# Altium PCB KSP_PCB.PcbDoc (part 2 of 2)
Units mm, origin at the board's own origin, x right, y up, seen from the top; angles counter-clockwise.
Board outline 121 x 121 mm, 2 copper layers (Top Layer, Bottom Layer), stack 1.571 mm thick; 210 components, 141 nets, 724 pads, 132 vias.
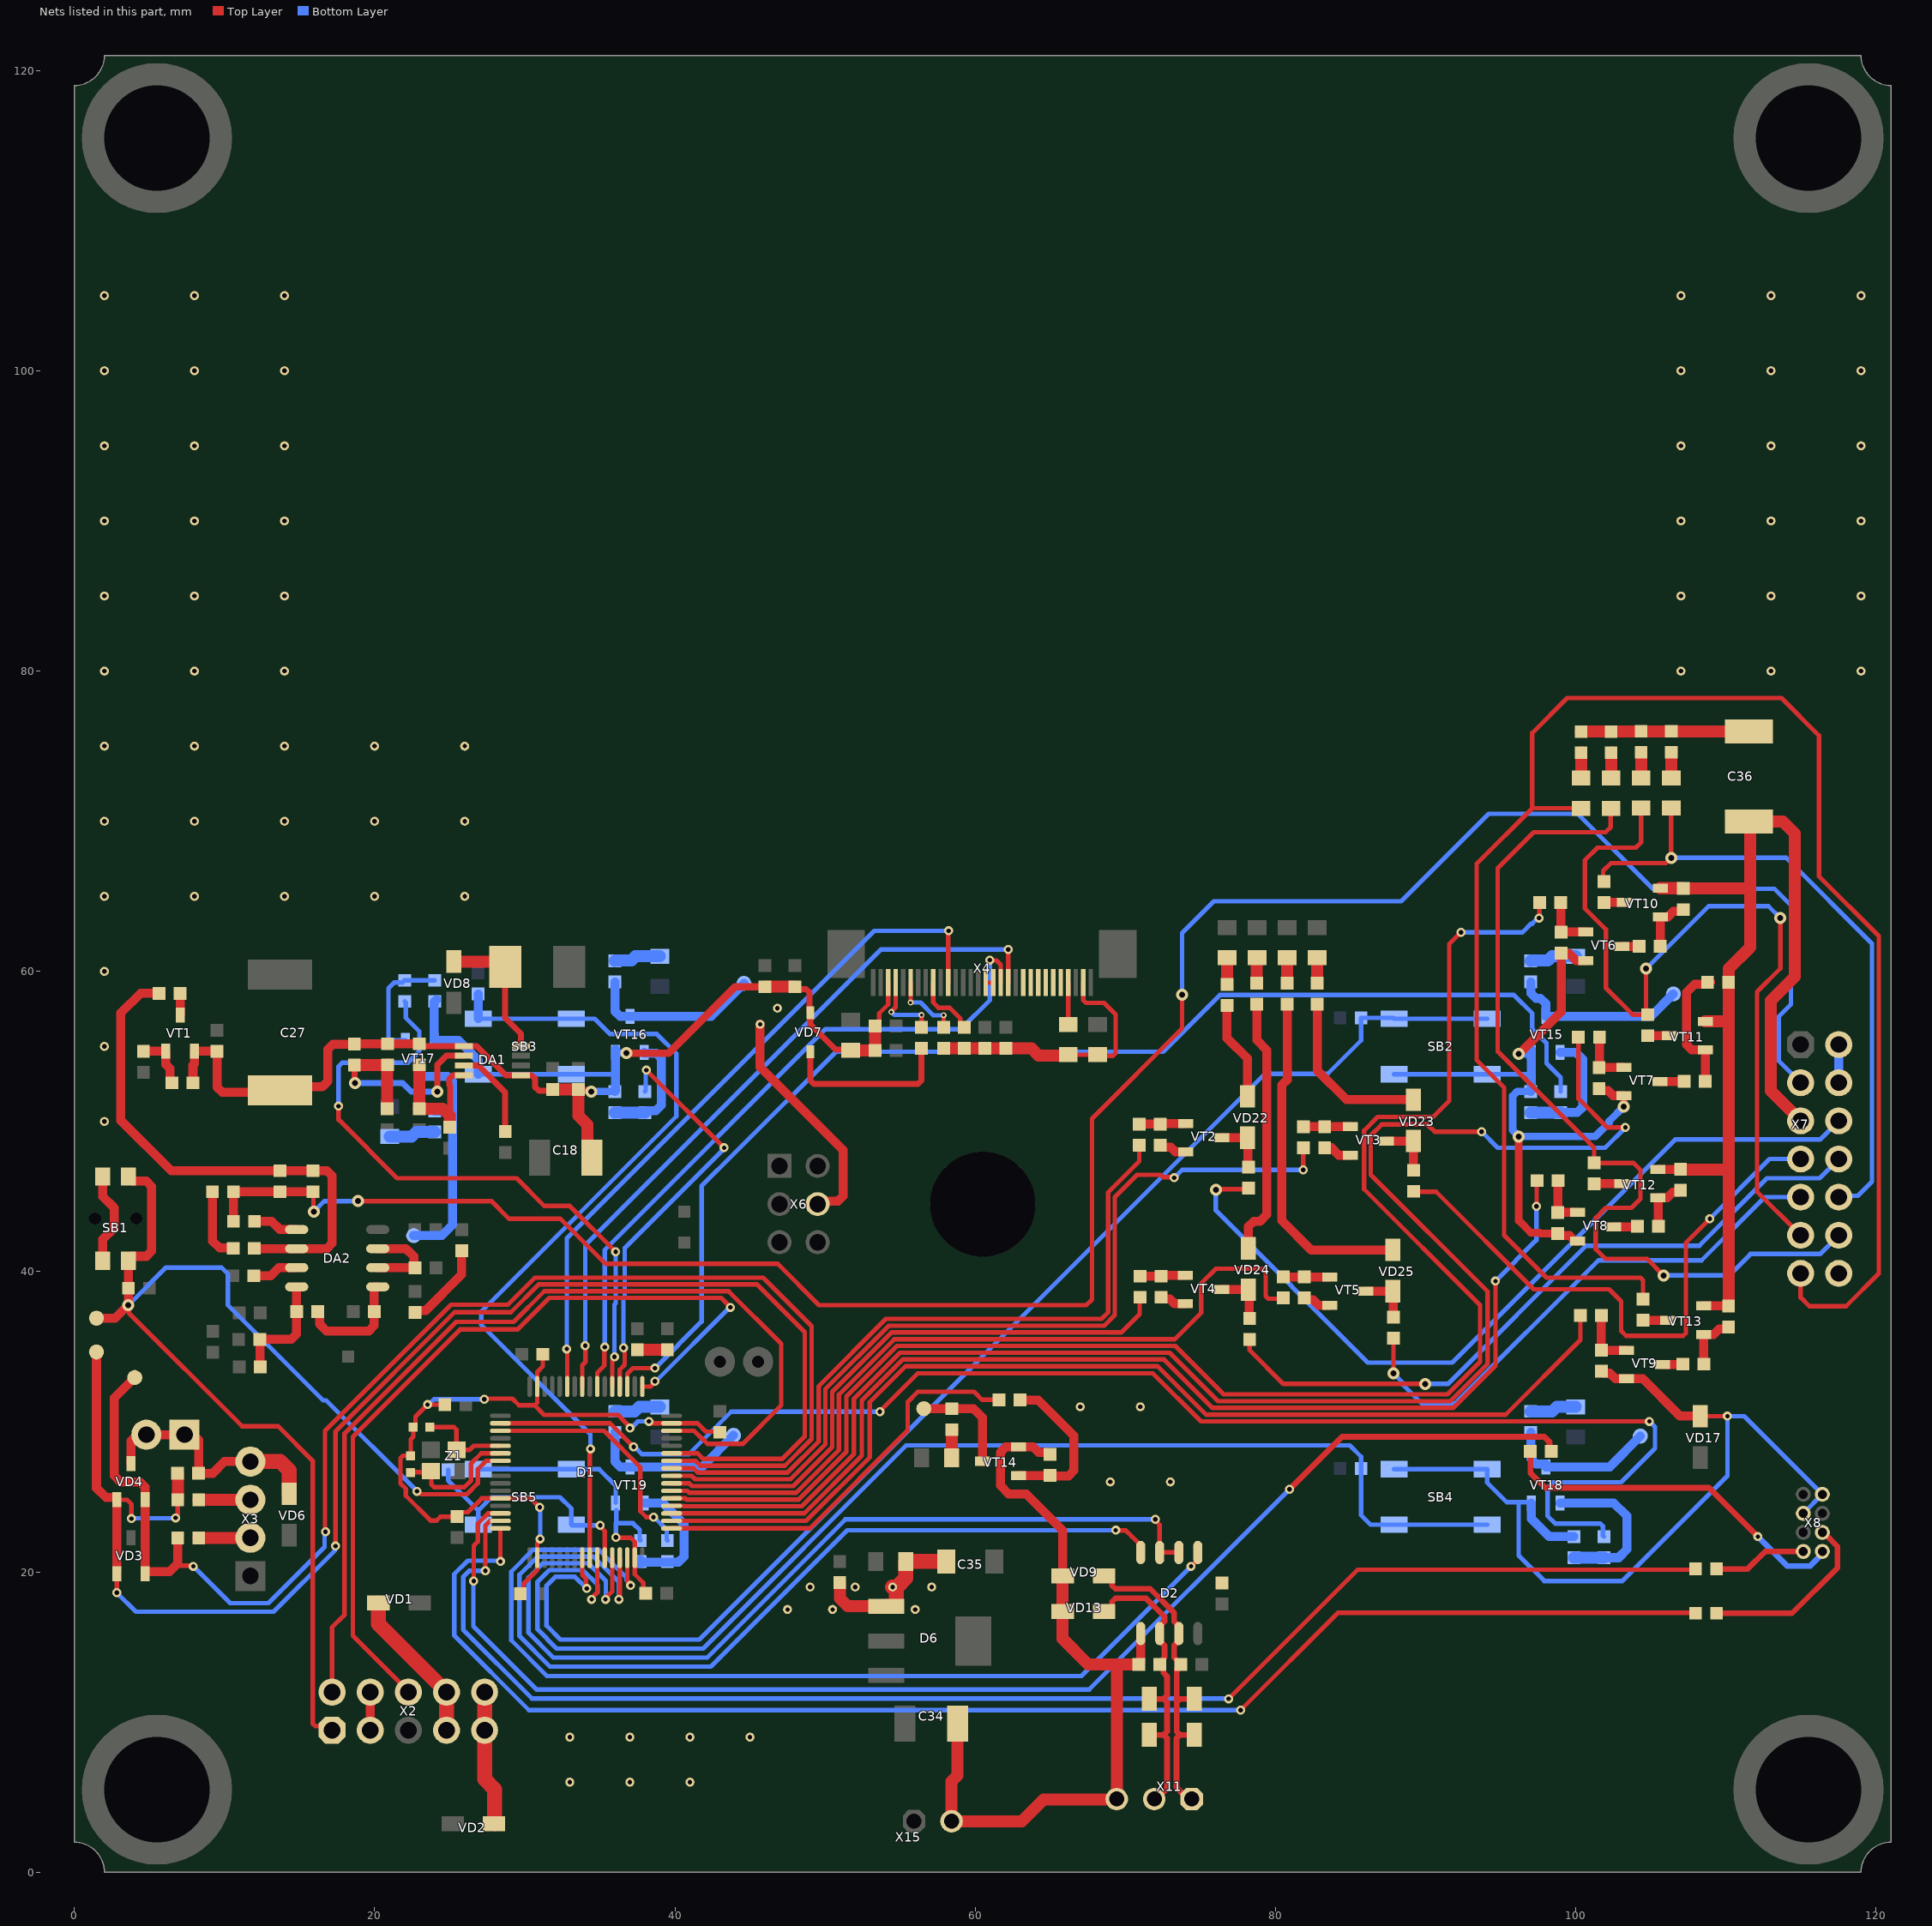
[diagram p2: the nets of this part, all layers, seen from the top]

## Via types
v1: diameter 0.6, hole 0.3, Top Layer to Bottom Layer, tented both sides, 85 vias
v2: diameter 0.8, hole 0.4, Top Layer to Bottom Layer, tented both sides, 42 vias
v3: diameter 0.4, hole 0.2, Top Layer to Bottom Layer, tented both sides, 4 vias
v4: diameter 0.6, hole 0.3, Top Layer to Bottom Layer, 1 vias

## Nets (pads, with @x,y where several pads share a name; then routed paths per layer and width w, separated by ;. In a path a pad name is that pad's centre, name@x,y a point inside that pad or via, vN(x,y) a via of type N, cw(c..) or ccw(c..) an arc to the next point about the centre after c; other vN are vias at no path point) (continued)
GND: C1.1 C2.1 C3.1 C4.1 C5.1 C6.1 C7.1 C8.1 C9.1 C10.1 C11.1 C12.1 C13.1 C14.1 C15.1 C16.1 C17.1 C18.2 C19.1 C20.1 C21.1 C22.1 C24.1 C25.1 C27.2 C28.1 C32.1 C33.1 C34.2 C35.2 C36.2 D1.12 D1.18 D1.31 D1.47 D1.63 D2.5 D6.1 DA1.1 DA1.5 DA2.4 pad.N@2,50 pad.N@2,55 pad.N@2,60 pad.N@2,65 pad.N@2,70 pad.N@2,75 pad.N@2,80 pad.N@2,85 pad.N@2,90 pad.N@2,95 pad.N@2,100 pad.N@2,105 pad.N@8,65 pad.N@8,70 pad.N@8,75 pad.N@8,80 pad.N@8,85 pad.N@8,90 pad.N@8,95 pad.N@8,100 pad.N@8,105 pad.N@14,65 pad.N@14,70 pad.N@14,75 pad.N@14,80 pad.N@14,85 pad.N@14,90 pad.N@14,95 pad.N@14,100 pad.N@14,105 pad.N@20,65 pad.N@20,70 pad.N@20,75 pad.N@26,65 pad.N@26,70 pad.N@26,75 pad.N@33,6 pad.N@33,9 pad.N@37,6 pad.N@37,9 pad.N@41,6 pad.N@41,9 pad.N@45,9 pad.N@45.675,56.475 pad.N@46.825,57.55 pad.N@47.5,17.5 pad.N@49,19 pad.N@50.5,17.5 pad.N@52,19 pad.N@54.5,19 pad.N@56,17.5 pad.N@57.1,19 pad.N@67,31 pad.N@69,26 pad.N@71,31 pad.N@73,26 pad.N@107,80 pad.N@107,85 pad.N@107,90 pad.N@107,95 pad.N@107,100 pad.N@107,105 pad.N@113,80 pad.N@113,85 pad.N@113,90 pad.N@113,95 pad.N@113,100 pad.N@113,105 pad.N@119,80 pad.N@119,85 pad.N@119,90 pad.N@119,95 pad.N@119,100 pad.N@119,105 R1.1 R4.2 R7.1 R8.1 R10.1 R12.2 R16.2 R17.1 R22.2 R23.2 R24.2 R26.2 R31.2 R43.2 R62.1 R63.1 R64.1 R65.1 R74.1 R75.1 R76.1 R77.1 R95.1 R100.1 R101.1 R111.1 R112.1 R113.1 SB1.2 SB2.2 SB3.2 SB4.2 SB5.2 VD4.3 VD6.1 VD7.2 VD9.1 VD13.1 VD17.1 VD26.2 VD27.2 VD28.2 VD29.2 VT1.3 VT2.3 VT3.3 VT4.3 VT5.3 VT6.3 VT7.3 VT8.3 VT9.3 VT14.3 VT15.3 VT16.3 VT17.3 VT18.3 VT19.3 X2.3 X2.4 X3.4 X4.2 X4.5 X4.6 X4.7 X4.8 X4.9 X4.10 X4.14 X4.15 X4.28 X5.1 X5.2 X6.4 X7.2 X7.4 X7.14 X8.2 X8.3 X11.3 X15.2 | length 429.8
  Top Layer w0.3: C1.1@22.4,27.725 22.375,27.75 21.901,27.75 21.725,27.574 21.725,25.9 22.075,25.55 22.075,25.075 23.725,23.425 24.137,23.425 24.387,23.675 25.625,23.675 25.625,23.825 25.775,23.975 26.214,23.975 27.139,24.9 D1.12@28.375,24.9 30.398,24.9 30.998,24.3 v1(31,24.3) ; C1.1@22.4,27.84 22.4,28.825 22.575,29 C4.1@22.575,29.65 22.725,29.8 22.725,30.35 v1(23.525,31.15) C8.1@24.675,31.15 ; v1(27.3,31.5) 27.35,31.55 29.165,31.55 29.615,31.1 30.649,31.1 ; C7.1@29.699,18.549 29.917,18.767 29.917,19.217 30.825,20.125 D1.18@30.825,20.95 30.825,21.919 31.025,22.119 v1(31.025,22.2) ; C3.1@31.2,34.5 31.2,33.7 30.825,33.325 D1.63@30.825,32.35 30.825,31.276 30.649,31.1 ; v4@36.1,22.25 36.132,22.282 37.042,22.282 37.325,21.999 D1.31@37.325,20.95 37.325,20.099 37.325,19.85 37.901,19.274 37.901,18.724 C6.1@38.05,18.575 ; v1(37,29.575) 37,29.656 36.518,30.138 36.518,30.157 36.221,30.454 31.295,30.454 30.649,31.1 ; v1(38.275,30.025) 38.356,30.025 38.481,29.9 D1.47@39.775,29.9 41.501,29.9 42.051,29.35 42.95,29.35 C5.1@43,29.3 ; C10.1@51.7,54.75 C10.1@51.725,54.725 ; C14.1@53.325,56.35 53.6,56.625 53.6,57.2 54.2,57.8 X4.28@54.2,59.25 ; X4.15@60.7,59.25 X4.14@61.2,59.25 ; C12.1@66.2,54.45 C11.1@68.15,54.45 68.225,54.375 69.174,54.375 69.35,54.551 69.35,57.125 68.575,57.9 67.376,57.9 67.2,58.076 X4.2@67.2,59.25 ; VD17.1@108.275,30.375 v1(110.1,30.375)
  Top Layer w0.4: R26.2@22.975,55.175 23.125,55.025 DA1.1@25.95,55.025 26.8,55.025 28.75,53.075 DA1.5@29.75,53.075 30.466,53.075 30.7,52.841 30.7,52.284 30.934,52.05 31.825,52.05 C24.1@31.85,52.075 ; C16.1@48,58.975 48.158,58.817 48.741,58.817 48.975,58.583 48.975,57.3 VD7.2@49.025,57.25 49.025,56.475 50.25,55.25 50.709,54.791 51.659,54.791 C10.1@51.7,54.75
  Top Layer w0.5: C20.1@33.575,52.05 33.582,52.057 34.368,52.057 v2(34.425,52) ; v2(36.775,54.55) 39.575,54.55 44,58.975 C17.1@46,58.975 ; v2(96.2,49) 96.2,43.4 97,42.6 97.6,42.6 97.66,42.54 R76.1@98.8,42.54 ; v2(103.2,51) VT7.3@103.2,51.715
  Top Layer w0.6: SB1.2@1.9,40.725 1.9,42.15 2.65,42.9 2.65,44.25 1.9,45 SB1.2@1.9,46.325 ; VD4.3@3.777,27.206 3.777,28.718 X5.2@4.2,29.141 ; X5.2@4.796,29.141 4.797,29.139 7.334,29.139 X5.1@7.336,29.141 ; X5.1@7.336,29.141 X5.1@7.336,29.141 ; R17.1@7.9,52.575 7.9,53.75 8,53.85 VT1.3@8,54.675 C22.1@9.5,54.675 9.5,52.301 9.851,51.95 13.575,51.95 C27.2@13.7,52.075 13.95,52.325 16.524,52.325 16.875,52.676 16.875,54.799 17.226,55.15 R12.2@18.65,55.15 18.662,55.163 20.862,55.163 C19.1@20.875,55.175 R26.2@22.975,55.175 ; R4.2@8.275,26.575 R4.2@8.283,26.575 ; C25.1@9.2,45.25 9.2,42.05 9.676,41.574 10.501,41.574 R16.2@10.575,41.5 ; X3.4@11.725,27.351 11.717,27.358 10.008,27.358 9.225,26.575 R4.2@8.283,26.575 ; R23.2@12.375,33.65 12.36,33.665 12.36,35.475 R24.2@12.344,35.491 14.449,35.491 14.8,35.842 R22.2@14.8,37.35 ; R22.2@14.7,37.375 14.808,37.483 DA2.4@14.808,38.994 ; X2.3@19.705,9.46 X2.4@19.705,12 ; C21.1@22.7,37.275 22.825,37.4 23.4,37.4 25.8,39.8 R31.2@25.8,41.4 ; pad.N@45.675,56.475 45.675,53.625 51.2,48.1 51.2,45.043 50.849,44.691 49.691,44.691 X6.4@49.5,44.5 ; R95.1@64.975,27.825 64.85,27.95 64.225,27.95 63.85,28.325 VT14.3@62.875,28.325 62.026,28.325 61.675,27.974 61.675,25.75 62.225,25.2 63.4,25.2 65.825,22.775 VD9.1@65.825,19.75 ; R43.2@70.9,13.85 71.025,13.975 71.025,14.85 71.02,15.005 D2.5@71.02,15.9 ; R62.1@72.325,48.425 72.45,48.3 73.025,48.3 73.35,47.975 VT2.3@74.025,47.975 ; R64.1@72.375,38.3 72.5,38.175 72.975,38.175 73.293,37.857 VT4.3@74.006,37.857 ; R65.1@81.925,38.25 81.951,38.276 81.951,38.224 82.05,38.125 82.5,38.125 82.875,37.75 VT5.3@83.625,37.75 ; R63.1@83.275,48.25 83.724,48.25 84.224,47.75 VT3.3@84.975,47.75 ; v2(96.2,54.5) 99.025,57.325 99.025,61.165 99.05,61.19 99.549,61.19 100.024,60.715 VT6.3@100.675,60.715 ; R76.1@98.8,42.54 98.925,42.415 99.574,42.415 99.925,42.064 99.925,42.04 VT8.3@100.125,42.04 ; R75.1@101.55,52.19 101.675,52.065 102.15,52.065 102.5,51.715 VT7.3@103.2,51.715 ; R77.1@101.7,33.365 101.825,33.24 102.25,33.24 102.625,32.865 VT9.3@103.375,32.865 104.46,32.865 106.95,30.375 VD17.1@108.275,30.375 ; X5.1@7.336,29.141 7.932,29.141 8.283,28.789 R4.2@8.283,26.575
  Top Layer w0.8: C24.1@31.85,52.125 C20.1@33.575,52.125 ; C20.1@33.575,52.05 33.575,50.4 34.175,49.8 34.175,47.9 C18.2@34.475,47.6 ; R1.1@37.5,34.8 C9.1@39.5,34.8 ; C17.1@46,58.975 C16.1@47.999,58.975 ; C33.1@50.975,19.3 51,19.275 51,18.225 51.5,17.725 54.05,17.725 D6.1@54.075,17.7 ; C10.1@51.725,54.725 C15.1@53.325,54.725 C14.1@53.325,56.35 ; C13.1@57.9,54.875 R7.1@62.05,54.875 63.75,54.875 64.225,54.4 66.15,54.4 C12.1@66.2,54.45 ; C34.2@58.825,9.9 58.825,6.431 58.425,6.031 X15.2@58.425,3.4 63.1,3.4 64.55,4.85 69.4,4.85 X11.3@69.425,4.875 69.425,13.85 ; VD9.1@65.825,19.75 VD13.1@65.825,17.375 65.825,15.55 67.525,13.85 69.425,13.85 ; R43.2@70.9,13.85 69.425,13.85 ; VD29.2@100.35,75.99 VD27.2@104.35,75.99 VD26.2@106.35,75.99 C36.2@110.8,75.99
  Top Layer w1: X3.4@11.725,27.351 13.714,27.351 14.3,26.765 VD6.1@14.3,25.2 ; D6.1@54.075,17.7 54.748,17.7 pad.N@54.748,18.848 ; pad.N@54.5,19 54.789,19 55.375,19.586 C32.1@55.375,20.7 C35.2@58.075,20.7
  Bottom Layer w0.3: v1(23.525,31.15) 23.606,31.15 23.956,31.5 v1(27.3,31.5) ; SB5.2@26.9,26.85 SB5.2@33.1,26.85 34.95,26.85 36.05,25.75 VT19.3@36.05,24.6 ; SB3.2@26.9,53.15 SB3.2@33.1,53.15 35.875,53.15 36.05,53.325 ; v1(31,24.3) 31.025,24.275 v1(31.025,22.2) ; v4(36.075,22.3) 36.075,23.244 37.206,23.244 37.651,22.799 37.651,22.149 R113.1@37.7,22.1 ; 36.1,23.194 VT19.3@36.1,24.116 ; v1(37,29.575) 37.081,29.575 37.531,30.025 v1(38.275,30.025) ; SB4.2@87.9,26.85 SB4.2@94.1,26.85 94.1,25.95 95.4,24.65 96.2,24.65 ; SB2.2@87.9,53.15 SB2.2@94.1,53.15 97,53.15 97.05,53.1 ; VT18.3@97.05,24.6 97,24.65 96.2,24.65 ; X8.3@115.15,23.905 X8.2@116.42,25.175 115.22,26.375 111.22,30.375 v1(110.1,30.375) 110.1,26.4 103.1,19.4 97.9,19.4 96.2,21.1 96.2,24.65
  Bottom Layer w0.5: v2(34.425,52) R101.1@36,52 ; VT16.3@36.05,54.6 36.075,54.575 36.75,54.575 v2(36.775,54.55) ; R100.1@97,52 96.093,52 95.8,51.707 95.8,49.4 v2(96.2,49) 101.3,49 102.221,49.921 102.221,50.021 v2(103.2,51)
  Bottom Layer w0.6: R111.1@24.125,58.125 R111.1@24,58 23.95,57.95 VT17.3@23.95,55.4 25.6,55.4 26.9,54.1 SB3.2@26.9,53.15 ; R101.1@36,52 36.05,52.05 36.05,53.325 VT16.3@36.05,54.6 VT16.3@36.05,54.8 ; v2(96.2,54.5) 96.238,54.538 VT15.3@97.05,54.538 ; R100.1@97,52 97.05,52.05 97.05,53.1 VT15.3@97.05,54.538 ; VT18.3@97.05,24.6 97.05,23.525 98.225,22.35 R112.1@99.874,22.35 ; VT15.3@97.05,54.8 VT15.3@97.05,54.6 VT15.3@97.05,54.538 ; X7.4@117.515,52.585 X7.2@117.515,55.125
IREF: R10.2 X4.22 | length 4.3
  Top Layer w0.3: X4.22@57.2,59.25 57.2,57.925 57.55,57.575 58.3,57.575 59,56.875 59,56.55 R10.2@59.275,56.275
KEY1: D1.24 R114.1 SB2.1 | length 89.2
  Top Layer w0.3: D1.24@33.825,20.95 33.825,19.8 34.068,19.557 34.068,18.957 v1(34.125,18.9)
  Bottom Layer w0.3: v1(34.125,18.9) 33.35,19.675 32.025,19.675 31.45,19.1 31.45,16.425 32.375,15.5 41.625,15.5 79.3,53.175 83.475,53.175 85.7,55.4 R114.1@85.7,56.9 87.85,56.9 SB2.1@87.9,56.85 SB2.1@94.1,56.85
KEY2: D1.25 R115.1 SB3.1 | length 57.8
  Top Layer w0.3: D1.25@34.325,20.95 34.325,28.15 v1(34.375,28.2)
  Bottom Layer w0.3: SB3.1@26.9,56.85 34.65,56.85 35.675,55.825 38.8,55.825 40.1,54.525 40.1,50.35 27.1,37.35 27.1,36.45 34.375,29.175 v1(34.375,28.2)
  Bottom Layer w0.6: SB3.1@26.9,56.85 R115.1@26.9,58.5
KEY3: D1.26 R116.1 SB4.1 | length 85.8
  Top Layer w0.3: v1(34.45,18.175) 34.45,18.256 34.825,18.631 D1.26@34.825,20.95
  Bottom Layer w0.3: v1(34.45,18.175) 34.45,18.251 34.85,18.651 34.85,19.15 33.875,20.125 31.625,20.125 30.85,19.35 30.85,16.175 32.125,14.9 41.875,14.9 55.4,28.425 84.95,28.425 85.7,27.675 R116.1@85.7,26.9 85.7,23.775 86.325,23.15 SB4.1@87.9,23.15 SB4.1@94.1,23.15
KEY4: D1.27 R117.1 SB5.1 | length 16.7
  Top Layer w0.3: v1(35.025,23.1) 35.025,23.019 35.325,22.719 D1.27@35.325,20.95
  Bottom Layer w0.3: R117.1@24.9,26.8 24.9,26.099 26.9,24.099 27.776,24.975 32.35,24.975 33.1,24.225 SB5.1@33.1,23.15 33.15,23.1 v1(35.025,23.1) ; SB5.1@26.9,23.15 26.9,24.175
KEY_LED1: D1.51 R98.2 | length 83.4
  Top Layer w0.3: D1.51@36.825,32.35 36.825,33.199 37.201,33.575 v1(38.675,33.575)
  Bottom Layer w0.3: v1(38.675,33.575) 41.775,36.675 41.775,45.7 44.025,47.95 50.725,54.65 72.525,54.65 76.3,58.425 95.875,58.425 97.1,57.2 97.1,56.175 97.375,55.9 98.05,55.225 98.05,53.875 99,52.925 R98.2@99,52
KEY_LED2: D1.52 R99.2 | length 27.6
  Top Layer w0.3: D1.52@36.325,32.35 36.325,33.475 36.65,33.8 36.65,34.725 36.632,34.743 36.632,34.868 v1(36.575,34.925) ; v1(38.1,53.425) v1(43.275,48.25)
  Bottom Layer w0.3: v1(36.575,34.925) 36.575,38.253 36.65,38.328 36.65,41.575 43.275,48.2 v1(43.275,48.25) ; R99.2@38,52 38.05,52.05 38.05,53.375 v1(38.1,53.425)
KEY_LED3: D1.53 R108.2 | length 44.2
  Top Layer w0.3: v1(17.6,51.025) 17.6,50.125 21.5,46.225 29.45,46.225 31.3,44.375 33,44.375 v1(36.05,41.325) ; D1.53@35.825,32.35 35.825,34.094 35.975,34.244 v1(35.975,34.325)
  Bottom Layer w0.3: v1(17.6,51.025) 17.6,53.674 17.851,53.925 22.225,53.925 22.975,54.675 22.975,56 22.076,56.899 22.076,57.924 R108.2@22,58 ; v1(35.975,34.325) 35.975,37.816 36.05,37.891 v1(36.05,41.325)
KEY_LED4: D1.2 R109.2 | length 97.7
  Top Layer w0.3: D1.2@28.375,29.9 35.675,29.9 v1(37.25,28.325) ; v1(53.65,30.675) 53.65,30.7 56.175,33.225 71.825,33.225 75.025,30.025 v1(104.9,30.025)
  Bottom Layer w0.3: v1(37.25,28.325) 37.331,28.325 37.806,27.85 40.925,27.85 43.75,30.675 v1(53.65,30.675) ; R109.2@101.874,22.35 101.801,22.423 101.801,23.049 101.625,23.225 98.625,23.225 98.125,23.725 98.125,25.6 98.5,25.975 103.025,25.975 105.275,28.225 105.275,29.65 v1(104.9,30.025)
KEY_LED5: D1.3 R110.2 | length 16.3
  Top Layer w0.3: D1.3@28.375,29.4 35.275,29.4 37.7,26.975 37.7,24.05 38.1,23.65 v1(38.575,23.65) v1@38.61,23.65
  Bottom Layer w0.3: v1(38.575,23.65) 38.61,23.65 39.46,22.799 39.46,22.14 R110.2@39.5,22.1
LCD_RES: D1.59 X4.20 | length 47.3
  Top Layer w0.3: v1(32.8,34.85) 32.825,34.825 D1.59@32.825,32.35 ; X4.20@58.2,59.25 58.2,62.675 v1(58.225,62.7)
  Bottom Layer w0.3: v1(32.8,34.85) 32.8,42.225 53.275,62.7 v1(58.225,62.7)
LED: D1.33 R94.2 | length 26.9
  Top Layer w0.3: D1.33@39.775,22.9 48.975,22.9 55.5,29.425 55.5,31.325 56.175,32 59.925,32 60.45,31.475 61.55,31.475 R94.2@61.575,31.45
LINE_A: D1.14 R102.2 | length 90
  Top Layer w0.3: v1(26.6,19.4) 26.6,21.75 26.875,22.025 26.875,23.223 27.552,23.9 D1.14@28.375,23.9
  Top Layer w0.4: v1(80.925,25.5) 84.425,29 97.899,29 98.25,28.649 98.25,28.15 R102.2@98.375,28.025
  Bottom Layer w0.3: v1(26.6,19.4) 26.575,19.375 26.575,16.375 30.775,12.175 67.6,12.175 v1(80.925,25.5)
LINE_A_P: R102.1 X8.8 | length 23.9
  Top Layer w0.381: R102.1@96.975,28.025 96.975,26.6 97.975,25.6 108.875,25.6 v1(112.125,22.35)
  Bottom Layer w0.381: v1(112.125,22.35) 114.075,20.4 115.623,20.4 116.42,21.197 X8.8@116.42,21.365
LINE_B: D1.15 R103.2 | length 97
  Top Layer w0.3: v1(27.375,20.075) 27.375,23.086 27.689,23.4 D1.15@28.375,23.4 ; v1(76.875,11.55) 85.475,20.15 R103.2@108.11,20.15
  Bottom Layer w0.3: v1(27.375,20.075) 26.3,20.075 25.9,19.675 25.9,16.15 30.475,11.575 76.85,11.575 v1(76.875,11.55)
LINE_B_P: R103.1 X8.7 | length 6.3
  Top Layer w0.381: R103.1@109.375,20.2 111.452,20.2 112.617,21.365 X8.7@115.15,21.365
LINE_Z: D1.16 R104.2 | length 97.3
  Top Layer w0.3: v1(28.375,20.7) D1.16@28.375,22.9 ; v1(77.675,10.8) 84.15,17.275 R104.2@108.096,17.275
  Bottom Layer w0.3: v1(28.375,20.7) 28.325,20.75 26.2,20.75 25.3,19.85 25.3,15.775 30.275,10.8 v1(77.675,10.8)
LINE_Z_P: R104.1 X8.6 | length 12.1
  Top Layer w0.381: R104.1@109.431,17.25 114.4,17.25 117.425,20.275 117.425,21.7 116.49,22.635 X8.6@116.42,22.635
MODBUS_N: D2.6 R38.1 R43.1 R50.1 VD13.2 X11.2 | length 20.6
  Top Layer w0.381: VD13.2@68.575,17.375 68.803,17.375 69.113,17.685 69.113,18.022 69.336,18.245 71.386,18.245 72.608,17.023 72.608,16.708 72.29,16.39 D2.6@72.29,15.9 72.29,15.41 72.608,15.092 72.608,14.308 72.535,14.235 72.535,14.084 R43.1@72.3,13.85 72.535,13.615 72.535,13.29 72.782,13.043 72.782,11.773 72.559,11.55 ; R38.1@71.6,9.15 72.559,9.15 ; R50.1@71.6,11.55 72.559,11.55 ; X11.2@71.925,4.875 72.072,4.875 72.775,5.578 72.775,8.934 72.559,9.15 ; 72.559,9.15 72.782,9.373 72.782,11.327 72.559,11.55
MODBUS_P: D2.7 R38.2 R42.1 R50.2 VD9.2 X11.1 | length 21.9
  Top Layer w0.381: VD9.2@68.575,19.75 68.803,19.75 69.113,19.441 69.113,19.103 69.336,18.88 71.649,18.88 73.243,17.286 73.243,16.708 73.56,16.39 D2.7@73.56,15.9 73.56,15.41 73.243,15.092 73.243,14.307 R42.1@73.7,13.85 73.466,13.615 73.466,13.44 73.417,13.392 73.417,11.327 ; X11.1@74.425,4.875 74.178,4.875 73.41,5.643 73.41,8.927 73.633,9.15 73.641,9.15 ; R38.2@74.6,9.15 73.641,9.15 ; R50.2@74.6,11.55 73.641,11.55 73.417,11.327 ; 73.417,11.327 73.417,9.373 73.641,9.15
MODBUS_RX: D1.30 D2.1 | length 66.6
  Top Layer w0.3: D1.30@36.825,20.95 36.825,19.406 37.05,19.181 v1(37.05,19.1) ; v1(74.375,20.375) 74.377,20.375 74.83,20.828 D2.1@74.83,21.3
  Bottom Layer w0.3: v1(37.05,19.1) 37.05,19.181 36.775,19.456 36.775,19.625 34.925,21.475 30.55,21.475 29.1,20.025 29.1,15.45 31.475,13.075 67.075,13.075 v1(74.375,20.375)
MODBUS_TRE: D1.28 D2.2 D2.3 | length 63.7
  Top Layer w0.3: v1(35.375,18.175) 35.375,18.256 35.825,18.706 D1.28@35.825,20.95 ; v1(72,23.5) 72,23.419 72.282,23.136 72.282,21.308 D2.3@72.29,21.3 D2.2@73.56,21.3
  Bottom Layer w0.3: v1(35.375,18.175) 35.4,18.2 35.4,19.4 34.225,20.575 31.2,20.575 30.25,19.625 30.25,15.95 31.9,14.3 42.15,14.3 51.35,23.5 v1(72,23.5)
MODBUS_TX: D1.29 D2.4 | length 62.7
  Top Layer w0.3: v1(36.275,18.175) 36.325,18.225 D1.29@36.325,20.95 ; v1(69.355,22.779) 69.377,22.758 70.037,22.758 70.425,22.37 71.02,21.775 D2.4@71.02,21.3
  Bottom Layer w0.3: v1(36.275,18.175) 36.275,19.325 34.575,21.025 30.85,21.025 29.65,19.825 29.65,15.725 31.675,13.7 42.4,13.7 51.479,22.779 v1(69.355,22.779)
MOSI: D1.57 X4.12 | length 48.1
  Top Layer w0.3: D1.57@33.825,32.35 33.825,33.775 34.05,34 34.05,35.05 v1(34.025,35.075) ; X4.12@62.2,59.25 v1(62.2,61.45)
  Bottom Layer w0.3: v1(34.025,35.075) 34.025,41.775 53.7,61.45 v1(62.2,61.45)
NetC1_2: C1.2 D1.6 Z1.3 | length 8.6
  Top Layer w0.3: C1.2@22.4,26.65 22.475,26.65 23.6,26.65 23.675,26.65 Z1.3@23.75,26.725 23.775,26.7 23.775,25.826 23.951,25.65 25.978,25.65 26.425,26.097 26.425,27.225 27.1,27.9 D1.6@28.375,27.9
NetC4_2: C4.2 D1.5 Z1.1 | length 6.2
  Top Layer w0.3: C4.2@23.675,29.65 25.274,29.65 25.45,29.474 Z1.1@25.45,28.125 26.325,28.125 26.6,28.4 D1.5@28.375,28.4
NetC19_2: C19.2 DA1.2 R11.2 R12.1 | length 15.9
  Top Layer w0.4: R12.1@18.65,53.75 18.675,53.725 18.675,52.575 v2(18.7,52.55) ; v2(24.175,52) 24.175,53.775 24.775,54.375 DA1.2@25.95,54.375
  Top Layer w0.8: R12.1@18.65,53.75 18.662,53.763 20.862,53.763 C19.2@20.875,53.775 ; R11.2@20.825,50.85 20.825,53.725 C19.2@20.85,53.75
  Bottom Layer w0.4: v2(18.7,52.55) 21.875,52.55 22.425,52 v2(24.175,52)
NetC23_2: C23.2 DA2.2 R16.1 R19.1 R20.2 | length 35.6
  Top Layer w0.6: R19.1@5.65,58.525 5.625,58.55 4.425,58.55 3.1,57.225 3.1,50.075 6.45,46.725 C23.2@15.869,46.725 ; R16.1@12.009,41.534 DA2.2@14.808,41.534 16.824,41.534 17.175,41.885 17.175,46.374 16.824,46.725 C23.2@15.9,46.725
NetC26_1: C26.1 DA1.4 R25.2 R26.1 | length 10.2
  Top Layer w0.4: C26.1@25,49.625 25.025,49.65 25.025,52.375 24.975,52.425 24.975,52.841 25.209,53.075 DA1.4@25.95,53.075
  Top Layer w0.8: R25.2@22.95,50.85 24.531,50.85 25,50.381 C26.1@25,49.625 ; R25.2@22.95,50.875 22.975,50.875 R26.1@22.975,53.775
NetDA1_3: DA1.3 R18.2 | length 6.1
  Top Layer w0.4: DA1.3@25.95,53.725 26.925,53.725 28.7,51.95 R18.2@28.7,49.325
NetDA1_8: DA1.8 L1.1 VD8.1 | length 9.3
  Top Layer w0.4: L1.1@28.7,60.3 28.7,56.9 29.75,55.85 DA1.8@29.75,55.025
  Top Layer w0.8: VD8.1@25.275,60.65 28.35,60.65 L1.1@28.7,60.3
NetDA2_1: DA2.1 R21.2 | length 3
  Top Layer w0.6: R21.2@12,43.35 13.15,43.35 13.696,42.804 DA2.1@14.808,42.804
NetDA2_3: DA2.3 R15.1 | length 3.1
  Top Layer w0.6: R15.1@11.95,39.725 13.075,39.725 13.614,40.264 DA2.3@14.808,40.264
NetDA2_5: DA2.5 R22.1 R27.2 | length 7.7
  Top Layer w0.6: R22.1@16.2,37.35 16.325,37.225 16.325,36.525 16.8,36.05 19.624,36.05 19.975,36.401 R27.2@19.975,37.35 19.975,38.994 DA2.5@20.208,38.994
NetDA2_6: DA2.6 DA2.7 R14.2 | length 5.8
  Top Layer w0.6: DA2.6@20.208,40.264 22.614,40.264 22.625,40.275 22.625,41 22.091,41.534 DA2.7@20.208,41.534 ; R14.2@22.65,40.3 R14.2@22.675,40.325
NetR3_1: R3.1 VD5.1 | length 1.9
  Top Layer w0.8: R3.1@58.425,27.6 58.45,27.625 58.45,29.45 VD5.1@58.475,29.475
NetR5_1: R5.1 X3.3 | length 3.4
  Top Layer w0.8: R5.1@8.283,24.806 8.285,24.808 11.722,24.808 X3.3@11.725,24.811
NetR6_1: R6.1 X3.2 | length 3.4
  Top Layer w0.8: R6.1@8.283,22.266 8.285,22.268 11.722,22.268 X3.2@11.725,22.271
NetR9_1: R9.1 VD7.1 | length 11.7
  Top Layer w0.4: VD7.1@49.025,54.65 49.025,52.734 49.259,52.5 56.191,52.5 56.425,52.734 R9.1@56.425,54.875
NetR13_1: R13.1 R17.2 VT1.1 | length 3.8
  Top Layer w0.6: R13.1@4.6,54.675 VT1.1@6.1,54.675 6.1,53.8 6.375,53.525 6.375,52.7 R17.2@6.5,52.575
NetR19_2: R19.2 VT1.2 | length 1.4
  Top Layer w0.6: VT1.2@7.05,57.075 R19.2@7.05,58.525
NetR54_1: R54.1 VD18.1 | length 1.8
  Top Layer w0.8: VD18.1@76.775,59.125 R54.1@76.775,60.925
NetR55_1: R55.1 VD19.1 | length 1.7
  Top Layer w0.8: VD19.1@82.775,59.225 R55.1@82.775,60.925
NetR56_1: R56.1 VD20.1 | length 1.7
  Top Layer w0.8: VD20.1@78.75,59.225 R56.1@78.75,60.925
NetR57_1: R57.1 VD21.1 | length 1.7
  Top Layer w0.8: VD21.1@80.775,59.225 R57.1@80.775,60.925
NetR58_1: R58.1 R62.2 VT2.1 | length 3.1
  Top Layer w0.6: R58.1@70.925,49.825 R62.2@72.325,49.825 72.375,49.875 VT2.1@74.025,49.875
NetR59_1: R59.1 R63.2 VT3.1 | length 3.1
  Top Layer w0.6: R59.1@81.85,49.65 R63.2@83.275,49.65 84.775,49.65 VT3.1@84.975,49.65
NetR60_1: R60.1 R64.2 VT4.1 | length 3.1
  Top Layer w0.6: R60.1@70.975,39.7 R64.2@72.375,39.7 72.432,39.757 VT4.1@74.006,39.757
NetR61_1: R61.1 R65.2 VT5.1 | length 3.1
  Top Layer w0.6: R61.1@80.525,39.65 R65.2@81.925,39.65 83.425,39.65 VT5.1@83.625,39.65
NetR66_2: R66.2 VD22.2 VT2.2 | length 3.7
  Top Layer w0.6: VT2.2@76.425,48.925 VD22.2@78.125,48.925 78.163,48.888 78.163,47.012 R66.2@78.2,46.975
NetR67_2: R67.2 VD23.2 VT3.2 | length 3.8
  Top Layer w0.6: VT3.2@87.375,48.7 VD23.2@89.175,48.7 89.188,48.688 89.188,46.762 R67.2@89.2,46.75
NetR68_2: R68.2 VD24.2 VT4.2 | length 3.8
  Top Layer w0.6: VT4.2@76.406,38.807 78.193,38.807 VD24.2@78.2,38.8 78.238,38.763 78.238,36.913 R68.2@78.275,36.875
NetR69_2: R69.2 VD25.2 VT5.2 | length 3.5
  Top Layer w0.6: VT5.2@86.025,38.7 VD25.2@87.825,38.7 87.838,38.688 87.838,36.988 R69.2@87.85,36.975
NetR70_1: R70.1 R74.2 VT6.1 | length 3.6
  Top Layer w0.6: R74.2@99,62.563 R70.1@99,64.538 ; R74.2@99.025,62.615 100.475,62.615 VT6.1@100.675,62.615
NetR71_1: R71.1 R75.2 VT7.1 | length 3.6
  Top Layer w0.6: R71.1@101.575,55.615 101.575,53.615 VT7.1@103.2,53.615
NetR72_1: R72.1 R76.2 VT8.1 | length 3.5
  Top Layer w0.6: R72.1@98.825,46.065 98.812,46.053 98.812,43.953 R76.2@98.8,43.94 99.925,43.94 VT8.1@100.125,43.94
NetR73_1: R73.1 R77.2 VT9.1 | length 4
  Top Layer w0.6: R73.1@101.7,37.09 R77.2@101.7,34.765 103.175,34.765 VT9.1@103.375,34.765
NetR78_1: R78.1 R82.2 VT10.1 | length 3.7
  Top Layer w0.6: R78.1@105.625,61.665 VT10.1@105.625,63.64 106.149,63.64 106.5,63.991 107.026,63.991 R82.2@107.15,64.115
NetR78_2: R78.2 VT6.2 | length 1.1
  Top Layer w0.6: VT6.2@103.075,61.665 R78.2@104.225,61.665
NetR79_1: R79.1 R83.2 VT11.1 | length 9.1
  Top Layer w0.6: R79.1@108.625,52.665 VT11.1@108.625,54.765 ; VT11.1@108.825,54.789 108.825,54.765 VT11.1@108.625,54.765 ; R83.2@108.975,59.275 108.85,59.15 107.925,59.15 107.375,58.6 107.375,55.116 107.726,54.765 VT11.1@108.625,54.765
NetR79_2: R79.2 VT7.2 | length 1.6
  Top Layer w0.6: VT7.2@105.6,52.665 R79.2@107.225,52.665
NetR80_1: R80.1 R84.2 VT12.1 | length 3.6
  Top Layer w0.6: VT12.1@105.475,44.915 VT12.1@105.487,44.915 ; R80.1@105.5,43.015 105.487,43.028 VT12.1@105.487,44.915 ; R84.2@106.975,45.415 106.85,45.29 106.462,45.29 106.087,44.915 VT12.1@105.487,44.915
NetR80_2: R80.2 VT8.2 | length 1.6
  Top Layer w0.6: VT8.2@102.525,42.99 R80.2@104.075,42.99
NetR81_1: R81.1 R85.2 VT13.1 | length 3.8
  Top Layer w0.6: R81.1@108.525,33.84 VT13.1@108.525,35.815 109.174,35.815 109.549,36.19 110.05,36.19 R85.2@110.175,36.315
NetR81_2: R81.2 VT9.2 | length 1.4
  Top Layer w0.6: VT9.2@105.775,33.815 106.151,33.815 106.164,33.802 107.087,33.802 R81.2@107.125,33.84
NetR86_2: R86.2 VT10.2 | length 1.4
  Top Layer w0.6: R86.2@101.875,64.59 VT10.2@103.225,64.59
NetR87_2: R87.2 VT11.2 | length 1.4
  Top Layer w0.6: R87.2@104.8,55.715 VT11.2@106.225,55.715
NetR88_2: R88.2 VT12.2 | length 1.8
  Top Layer w0.6: R88.2@101.25,45.865 VT12.2@103.075,45.865
NetR89_2: R89.2 VT13.2 | length 1.7
  Top Layer w0.6: R89.2@104.475,36.765 105.925,36.765 VT13.2@106.125,36.765
NetR90_1: R90.1 VD26.1 | length 1.7
  Top Layer w0.8: R90.1@106.35,72.89 VD26.1@106.35,74.59
NetR91_1: R91.1 VD27.1 | length 1.7
  Top Layer w0.8: R91.1@104.35,72.89 VD27.1@104.35,74.59
NetR92_1: R92.1 VD28.1 | length 1.7
  Top Layer w0.8: R92.1@102.35,72.865 VD28.1@102.35,74.565
NetR93_1: R93.1 VD29.1 | length 1.7
  Top Layer w0.8: R93.1@100.35,72.865 VD29.1@100.35,74.565
NetR94_1: R94.1 R95.2 VT14.1 | length 10.8
  Top Layer w0.6: VT14.1@62.875,26.425 63.075,26.425 R95.2@64.975,26.425 65,26.4 66.224,26.4 66.575,26.751 66.575,29.075 64.2,31.45 R94.1@62.975,31.45
NetR96_1: R96.1 VD30.1 | length 3.1
  Bottom Layer w0.8: VD30.1@97,60.7 97.025,60.725 98.15,60.725 98.425,61 R96.1@100,61
NetR97_1: R97.1 VD31.1 | length 3.1
  Bottom Layer w0.8: VD31.1@36,60.7 36.025,60.725 37.1,60.725 37.375,61 R97.1@39,61
NetR98_1: R98.1 R100.2 VT15.1 | length 8.5
  Bottom Layer w0.6: VT15.1@98.95,54.6 100,54.6 100.45,54.15 100.45,50.951 100.099,50.6 R98.1@99,50.6
  Bottom Layer w0.8: R100.2@97,50.6 R98.1@99,50.6
NetR99_1: R99.1 R101.2 VT16.1 | length 7.8
  Bottom Layer w0.6: VT16.1@37.95,54.6 37.95,54.55 38.749,54.55 39.1,54.199 39.1,51.101 38.724,50.725 38.125,50.725 R99.1@38,50.6
  Bottom Layer w0.8: R101.2@36,50.6 R99.1@38,50.6
NetR105_1: R105.1 VD32.1 | length 3.1
  Bottom Layer w0.8: R105.1@21,49 22.475,49 22.775,49.3 VD32.1@24,49.3
NetR106_1: R106.1 VD33.1 | length 3.1
  Bottom Layer w0.8: VD33.1@97,30.7 98.425,30.7 98.725,31 R106.1@100,31
NetR107_1: R107.1 VD34.1 | length 3.1
  Bottom Layer w0.8: VD34.1@36,30.7 37.325,30.7 37.625,31 R107.1@39,31
NetR108_1: R108.1 R111.2 VT17.1 | length 7.8
  Bottom Layer w0.3: R108.1@21.997,59.397 21.851,59.251 21.301,59.251 20.925,58.875 20.925,55.576 21.101,55.4 VT17.1@22.05,55.4 ; R108.1@22,59.4 R111.2@24,59.4
NetR109_1: R109.1 R112.2 VT18.1 | length 10.8
  Bottom Layer w0.6: VT18.1@98.95,24.6 102.525,24.6 103.4,23.725 103.4,21.5 102.85,20.95 R109.1@101.874,20.95
  Bottom Layer w0.8: R112.2@99.874,20.95 R109.1@101.874,20.95
NetR110_1: R110.1 R113.2 VT19.1 | length 8.5
  Bottom Layer w0.6: R113.2@37.75,20.675 37.763,20.663 39.05,20.663 40.249,20.663 40.6,21.014 40.6,23.199 39.199,24.6 VT19.1@37.95,24.6
  Bottom Layer w0.8: R113.2@37.7,20.7 R113.2@37.725,20.675
NetTP4_0: TP4.0 VD5.2 VT14.2 | length 7.2
  Top Layer w0.6: TP4.0@56.39,30.875 VD5.2@58.45,30.875 ; VD5.2@58.475,30.875 59.875,30.875 60.475,30.275 VT14.2@60.475,27.375
NetTP5_0: TP5.0 VD30.2 VT15.2 | length 12
  Bottom Layer w0.6: VD30.2@97,59.3 97,58.551 97.351,58.2 97.649,58.2 98,57.849 VT15.2@98,57 105,57 TP5.0@106.5,58.5
NetTP6_0: TP6.0 VD31.2 VT16.2 | length 11.6
  Bottom Layer w0.6: VD31.2@36,59.3 36,57.351 36.351,57 VT16.2@37,57 42.4,57 TP6.0@44.6,59.2
NetTP7_0: TP7.0 VD32.2 VT17.2 | length 16.1
  Bottom Layer w0.6: TP7.0@22.6,42.4 24.475,42.4 25.2,43.125 25.2,51.051 ; VT17.2@23,53 24.849,53 25.2,52.649 25.2,51.051 ; VD32.2@24,50.7 24.849,50.7 25.2,51.051
NetTP8_0: TP8.0 VD33.2 VT18.2 | length 10.2
  Bottom Layer w0.6: VD33.2@97,29.3 97,27.551 97.351,27.2 98,27.2 VT18.2@98,27 102.249,27 TP8.0@104.3,29.051
NetTP9_0: TP9.0 VD34.2 VT19.2 | length 10.9
  Bottom Layer w0.6: VD34.2@36,29.3 36,27.351 36.351,27 VT19.2@37,27 41.8,27 TP9.0@43.9,29.1
NetVD1_1: VD1.1 X2.7 X2.8 | length 10.6
  Top Layer w1: VD1.1@20.25,17.95 20.25,16.535 X2.8@24.785,12 ; X2.7@24.785,9.46 X2.8@24.785,12.216
NetVD2_1: VD2.1 X2.9 X2.10 | length 9.1
  Top Layer w1: X2.10@27.325,12.093 X2.9@27.325,9.46 27.325,6.2 28,5.525 VD2.1@28,3.225
NetVD18_2: VD18.2 VD22.1 | length 6.6
  Top Layer w0.6: VD18.2@76.775,57.725 76.775,55.55 78.125,54.2 VD22.1@78.125,51.675
NetVD19_2: VD19.2 VD23.1 | length 11.6
  Top Layer w0.6: VD19.2@82.775,57.825 82.775,53.4 84.725,51.45 VD23.1@89.175,51.45
NetVD20_2: VD20.2 VD24.1 | length 17.3
  Top Layer w0.6: VD24.1@78.2,41.55 78.2,42.999 78.551,43.35 78.975,43.35 79.425,43.8 79.425,54.75 78.75,55.425 VD20.2@78.75,57.825
NetVD21_2: VD21.2 VD25.1 | length 22.8
  Top Layer w0.6: VD21.2@80.775,57.825 80.775,52.775 80.425,52.425 80.425,43.4 82.375,41.45 VD25.1@87.825,41.45
RK_HIGH_1: R86.1 R90.2 X7.10 | length 43.2
  Top Layer w0.3: R86.1@101.875,65.99 101.826,66.039 101.826,66.689 102.351,67.215 105.999,67.215 v2(106.35,67.566) R90.2@106.35,70.89
  Bottom Layer w0.3: v2(106.35,67.566) 114.009,67.566 119.725,61.85 119.725,46 118.775,45.05 117.6,45.05 X7.10@117.515,44.965
RK_HIGH_2: R87.1 R91.2 X7.11 | length 56.2
  Top Layer w0.3: R91.2@104.35,70.89 104.35,68.591 103.999,68.24 101.44,68.24 100.6,67.4 100.6,64.2 102,62.8 102,58.899 103.784,57.115 104.675,57.115 R87.1@104.8,57.115 104.675,57.24 v2@104.675,60.121 ; v2(113.625,63.55) 113.625,60.2 112.075,58.65 112.075,45.325 X7.11@114.975,42.425
  Bottom Layer w0.3: v2(104.675,60.175) 108.845,64.345 112.83,64.345 v2(113.625,63.55)
RK_HIGH_3: R88.1 R92.2 X7.12 | length 61
  Top Layer w0.3: R92.2@102.35,70.865 102.35,70.69 102.325,70.665 102.325,69.616 101.974,69.265 97.2,69.265 94.8,66.865 94.8,54.665 100.365,49.1 100.375,49.1 101.225,48.25 R88.1@101.225,47.24 103.835,47.24 104.3,46.775 104.3,44.85 103.7,44.25 102,44.25 101.325,43.575 101.325,41.5 101.975,40.85 104.75,40.85 v2(105.85,39.75)
  Bottom Layer w0.3: v2(105.85,39.75) 110.21,39.75 111.635,41.175 116.265,41.175 X7.12@117.515,42.425
RK_HIGH_4: R89.1 R93.2 X7.13 | length 117.3
  Top Layer w0.3: R93.2@100.35,70.865 97.1,70.865 ; R89.1@104.475,38.165 104.475,39.424 104.299,39.6 98.05,39.6 95.225,42.425 95.225,52.265 93.4,54.09 93.4,67.165 97.1,70.865 ; X7.13@114.975,39.885 114.975,38.275 115.55,37.7 118,37.7 120.175,39.875 120.175,62.35 116.2,66.325 116.2,75.7 113.7,78.2 99.425,78.2 97.1,75.875 97.1,70.865
RK_HIGH_UPR_1: D1.37 R70.2 | length 105.8
  Top Layer w0.3: D1.37@39.775,24.9 40.695,24.9 40.77,24.825 48.255,24.825 51.425,27.995 51.425,31.679 54.796,35.05 73.325,35.05 76.55,31.825 91.452,31.825 93.626,33.999 93.626,37.767 85.9,45.493 85.9,49.4 86.8,50.3 90.5,50.3 91.575,51.375 91.575,61.825 v1(92.35,62.6) ; v1(97.55,63.55) 97.575,63.575 97.575,64.565 R70.2@97.6,64.59
  Bottom Layer w0.3: v1(92.35,62.6) 96.45,62.6 97.025,63.175 97.094,63.175 97.469,63.55 v1(97.55,63.55)
RK_HIGH_UPR_2: D1.36 R71.2 | length 108
  Top Layer w0.3: D1.36@39.775,24.4 40.559,24.4 40.584,24.375 48.441,24.375 51.925,27.859 51.925,31.543 54.982,34.6 72.95,34.6 76.175,31.375 91.639,31.375 94.125,33.861 94.125,38.676 86.35,46.451 86.35,49.075 87.075,49.8 90.122,49.8 90.597,49.325 v1(93.725,49.325) ; R71.2@100.175,55.615 100.175,51.525 102.1,49.6 v1(103.3,49.6)
  Bottom Layer w0.3: v1(93.725,49.325) 94.8,48.25 101.95,48.25 v1(103.3,49.6)
RK_HIGH_UPR_3: D1.35 R72.2 | length 77.2
  Top Layer w0.3: D1.35@39.775,23.9 48.603,23.9 52.45,27.747 52.45,31.432 55.168,34.15 72.575,34.15 75.8,30.925 91.825,30.925 94.65,33.75 v1(94.65,39.375) ; v1(97.375,44.35) 97.4,44.375 97.4,46.04 R72.2@97.425,46.065
  Bottom Layer w0.3: v1(94.65,39.375) 97.375,42.1 v1(97.375,44.35)
RK_HIGH_UPR_4: D1.34 R73.2 | length 72
  Top Layer w0.3: D1.34@39.775,23.4 48.739,23.4 52.975,27.636 52.975,31.32 55.355,33.7 72.15,33.7 75.375,30.475 95.325,30.475 100.3,35.45 R73.2@100.3,37.09
RK_LOW_1: R66.1 X7.6 | length 56
  Top Layer w0.3: v2@76.063,45.488 R66.1@78.113,45.488
  Top Layer w0.6: v2(76.025,45.45) v2@76.063,45.488 ; R66.1@78.113,45.488 R66.1@78.2,45.575
  Bottom Layer w0.3: v2(76.025,45.45) 76.025,44.075 86.15,33.95 91.775,33.95 106.625,48.8 116.27,48.8 X7.6@117.515,50.045
RK_LOW_2: R67.1 X7.7 | length 39.3
  Top Layer w0.3: R67.1@89.2,45.35 89.225,45.325 90.699,45.325 97.199,38.825 102.225,38.825 103.025,38.025 103.025,36.05 103.35,35.725 107.149,35.725 107.325,35.901 107.325,41.925 v1(108.925,43.525)
  Bottom Layer w0.3: v1(108.925,43.525) 112.905,47.505 X7.7@114.975,47.505
RK_LOW_3: R68.1 X7.8 | length 47.1
  Top Layer w0.3: R68.1@78.274,35.474 78.274,34.776 80.525,32.525 v2(89.975,32.525)
  Bottom Layer w0.3: v2(89.975,32.525) 91.475,32.525 100.675,41.725 108.225,41.725 112.725,46.225 116.235,46.225 X7.8@117.515,47.505
RK_LOW_4: R69.1 X7.9 | length 36.1
  Top Layer w0.3: v2(87.863,33.225) 87.856,33.231 87.856,35.458 R69.1@87.912,35.513
  Top Layer w0.6: R69.1@87.85,35.575 R69.1@87.912,35.513
  Bottom Layer w0.3: v2(87.863,33.225) 88.501,32.587 88.501,32.449 89.725,31.225 91.975,31.225 101.5,40.75 108.375,40.75 112.59,44.965 X7.9@114.975,44.965
RK_LOW_UPR_1: D1.41 R58.2 | length 47.8
  Top Layer w0.3: D1.41@39.775,26.9 41.241,26.9 41.516,26.625 47.509,26.625 49.575,28.691 49.575,32.375 54.05,36.85 68.411,36.85 68.85,37.289 68.85,45.276 70.925,47.351 R58.2@70.925,48.425
RK_LOW_UPR_2: D1.40 R59.2 | length 59.1
  Top Layer w0.3: D1.40@39.775,26.4 41.104,26.4 41.329,26.175 47.696,26.175 50.025,28.504 50.025,32.189 54.236,36.4 68.597,36.4 69.3,37.103 69.3,44.975 70.775,46.45 72.344,46.45 72.494,46.3 73.2,46.3 v1(73.244,46.256) ; v1(81.85,46.775) R59.2@81.85,48.25
  Bottom Layer w0.3: v1(73.244,46.256) 73.267,46.256 73.786,46.775 v1(81.85,46.775)
RK_LOW_UPR_3: D1.39 R60.2 | length 39.3
  Top Layer w0.3: D1.39@39.775,25.9 40.968,25.9 41.143,25.725 47.882,25.725 50.475,28.318 50.475,32.002 54.423,35.95 69.725,35.95 70.95,37.175 70.95,38.275 R60.2@70.975,38.3
RK_LOW_UPR_4: D1.38 R61.2 | length 52.1
  Top Layer w0.3: D1.38@39.775,25.4 40.832,25.4 40.957,25.275 48.068,25.275 50.925,28.132 50.925,31.816 54.609,35.5 73.3,35.5 75.05,37.25 75.05,39.225 76.025,40.2 79.174,40.2 79.35,40.024 79.35,38.376 79.526,38.2 80.475,38.2 R61.2@80.525,38.25
RX: D1.43 R4.1 R5.2 TP3.0 VD3.1 VD4.1 | length 103
  Top Layer w0.3: v1(2.825,18.625) 2.826,18.626 VD3.1@2.827,19.866 VD3.1@2.827,19.866 VD3.1@2.827,20.066 ; VD4.1@2.827,24.806 3.519,24.806 3.8,24.525 v1(3.8,23.55) ; v1(6.75,23.6) 6.75,23.681 6.883,23.814 R5.2@6.883,24.806 ; v1(17.4,21.725) 17.4,29.375 25.325,37.3 29.075,37.3 30.925,39.15 45.475,39.15 48.65,35.975 48.65,29.039 47.136,27.525 41.889,27.525 41.514,27.9 D1.43@39.775,27.9
  Top Layer w0.6: TP3.0@1.475,34.65 1.475,25.6 2.112,24.963 2.827,24.963 VD4.1@2.827,24.806 VD3.1@2.827,20.066
  Top Layer w0.8: R5.2@6.883,24.806 6.892,24.814 R4.1@6.892,26.575
  Bottom Layer w0.3: v1(2.825,18.625) 4.1,17.35 13.275,17.35 17.343,21.418 17.343,21.668 v1(17.4,21.725) ; v1(3.8,23.55) 3.825,23.575 6.725,23.575 v1(6.75,23.6)
SCK: D1.55 X4.13 | length 46.6
  Top Layer w0.3: D1.55@34.825,32.35 34.825,33.275 35.3,33.75 35.3,34.95 v1(35.325,34.975) ; v1(60.975,60.75) 60.993,60.732 61.418,60.732 61.7,60.45 X4.13@61.7,59.25
  Bottom Layer w0.3: v1(35.325,34.975) 35.325,41.449 50.026,56.15 59.05,56.15 60.975,58.075 v1(60.975,60.75)
SPEED_CONTROL: C23.1 C25.2 R20.1 R21.1 X7.3 | length 149.7
  Top Layer w0.3: C23.1@15.9,45.325 15.925,45.3 15.925,44.025 v2(15.95,44) ; v2(18.9,44.7) 27.775,44.7 28.95,43.525 32.375,43.525 35.375,40.525 46.85,40.525 49.6,37.775 67.4,37.775 67.775,38.15 67.775,50.2 73.775,56.2 v2(73.775,58.45)
  Top Layer w0.6: R21.1@10.6,43.35 10.6,45.281 10.644,45.325 R20.1@13.7,45.325 C23.1@15.9,45.325
  Bottom Layer w0.3: v2(15.95,44) 16.65,44.7 v2(18.9,44.7) ; v2(73.775,58.45) 73.775,62.55 75.9,64.675 88.375,64.675 94.2,70.5 100.125,70.5 105.125,65.5 113.225,65.5 114.325,64.4 114.325,57.8 113.525,57 113.525,54.035 X7.3@114.975,52.585
SWCLK: D1.49 X2.6 | length 56.3
  Top Layer w0.3: X2.6@22.572,11.728 18.55,15.75 18.55,29 25.7,36.15 29.525,36.15 31.625,38.25 43.075,38.25 v1(43.7,37.625) ; D1.49@37.825,32.35 38.361,32.35 38.675,32.664 v1(38.675,32.7)
  Bottom Layer w0.3: v1(38.675,32.7) 38.725,32.7 43.65,37.625 v1(43.7,37.625)
SWDIO: D1.46 X2.2 | length 64.8
  Top Layer w0.3: X2.2@17.165,12 17.165,16.315 18,17.15 18,29.225 25.425,36.65 29.25,36.65 31.3,38.7 43.575,38.7 47.075,35.2 47.075,31.101 44.499,28.525 42.18,28.525 41.855,28.85 41.818,28.85 41.268,29.4 D1.46@39.775,29.4
TX: D1.42 R6.2 TP2.0 VD3.3 VD4.2 | length 95.2
  Top Layer w0.3: 6.742,20.417 7.883,20.417 v1(7.925,20.375) ; v1(16.725,22.675) 16.7,22.7 16.7,29.4 25.1,37.8 28.875,37.8 30.675,39.6 45.875,39.6 49.1,36.375 49.1,28.852 47.323,27.075 41.702,27.075 41.377,27.4 D1.42@39.775,27.4
  Top Layer w0.6: TP2.0@4.025,32.95 2.65,31.575 2.65,26.425 3.075,26 4.376,26 4.727,25.649 VD4.2@4.727,24.806 4.727,20.066 4.727,20.016 6.341,20.016 6.742,20.417 6.883,20.558 R6.2@6.883,22.266
  Bottom Layer w0.3: v1(7.925,20.375) 10.375,17.925 12.925,17.925 16.668,21.668 16.668,22.618 v1(16.725,22.675)
uC_RES: D1.7 R2.1 SB1.1 TP1.0 X2.1 | length 84.4
  Top Layer w0.3: v2(3.6,37.775) 3.651,37.724 3.651,37.224 11.175,29.7 13.575,29.7 15.875,27.4 15.875,9.908 16.051,9.732 17.365,9.732 X2.1@17.638,9.46 ; v1(22.825,25.375) 22.906,25.375 23.106,25.175 26.139,25.175 26.875,25.911 26.875,26.85 27.425,27.4 D1.7@28.375,27.4
  Top Layer w0.6: TP1.0@1.475,36.9 2.725,36.9 v2(3.6,37.775) R2.1@3.6,38.9 SB1.1@3.6,40.725 ; SB1.1@3.6,40.825 3.8,41.025 4.799,41.025 5.15,41.376 5.15,45.674 4.799,46.025 3.8,46.025 3.6,46.225 SB1.1@3.6,46.325
  Bottom Layer w0.3: v2(3.6,37.775) 6.1,40.275 9.8,40.275 10.225,39.85 10.225,37.775 16.565,31.435 16.765,31.435 v1(22.825,25.375)
Vcc_RK: C36.1 R82.1 R83.1 R84.1 R85.1 VT10.3 VT11.3 VT12.3 VT13.3 X7.5 | length 70.7
  Top Layer w0.6: VT12.3@105.475,46.815 R84.1@106.975,46.815 ; VT13.3@108.525,37.715 R85.1@110.175,37.715
  Top Layer w0.8: VT10.3@105.625,65.54 107.125,65.54 R82.1@107.15,65.515 111.625,65.515 ; R84.1@106.975,46.815 107,46.79 110.175,46.79 ; VT11.3@108.625,56.665 110.025,56.665 ; R85.1@110.175,37.715 110.175,46.79 ; C36.1@111.2,69.865 111.625,69.44 111.625,65.515 ; C36.1@111.525,69.99 111.54,69.975 113.781,69.975 114.575,69.181 114.575,59.65 112.975,58.05 112.975,52.045 X7.5@114.975,50.045 ; 110.175,46.79 110.175,56.665 R83.1@110.175,59.275 110.2,59.3 110.2,60.175 111.625,61.6 111.625,65.515
VCOMH: C12.2 X4.4 | length 2.5
  Top Layer w0.3: C12.2@66.2,56.775 66.2,58.5 X4.4@66.2,59.25
VDD: C13.2 X4.25 | length 4.7
  Top Layer w0.3: v3(55.7,57.925) 55.7,58.5 X4.25@55.7,59.25 ; C13.2@57.9,56.275 v3(57.9,57.075)
  Bottom Layer w0.3: v3(55.7,57.925) 56.35,57.925 57.2,57.075 v3(57.9,57.075)
VSL: R9.2 X4.27 | length 5
  Top Layer w0.3: v3(54.404,57.296) 54.404,57.324 54.7,57.62 X4.27@54.7,59.25 ; R9.2@56.425,56.275 v3(56.425,57.1)
  Bottom Layer w0.3: v3(54.404,57.296) 54.431,57.296 54.627,57.1 v3(56.425,57.1)
pads on no net: C18. C27. C34. C35. C36. D1. D1.1@28.675,32.05 D1.4 D1.8 D1.44 D1.45 D1.50 D1.54 D1.62 D2.28 D6. DA1. DA2.28 SB1.360 SB1.N VD1. VD2. VD3. VD4. VD6. VD7.5 VD8. VD9. VD13. VD17. VD22. VD23. VD24. VD25. VT1. VT2. VT3. VT4. VT5. VT6. VT7. VT8. VT9. VT10. VT11. VT12. VT13. VT14. VT15. VT16. VT17. VT18. VT19. X2.5 X4.1 X4.11 X4.21 X4.23 X4.30 X4.N X6.6 X7.38 X8.4 X8.5 X11.28 X15.23 X15.24 Z1.2 Z1.4 Z1.5 Z1.6
copper on no net: | length 65.6
  Top Layer w0.3: 18.225,34.35 v1(19.1,34.35) ; v1(26.925,29.275) 27.3,28.9 28.375,28.9 ; 39.775,28.4 41.65,28.4 42.075,27.975 46.95,27.975 47.95,28.975 47.95,31.375 47.95,35.2 v1(45.375,37.775) ; 39.775,28.9 38.025,28.9 37.65,29.275 37.65,30.624 37.826,30.8 38.475,30.8 39.388,31.713 40.039,32.364 v1(40.675,33) ; 40.625,41.925 40.85,41.9 42.425,41.9 v1(42.45,41.875) ; 40.628,44.006 41.5,44 v1(42.55,44)
  Bottom Layer w0.3: v1(19.1,34.35) 20.725,35.975 24.175,35.975 28.05,32.1 28.05,30.4 v1(26.925,29.275) ; v1(40.675,33) 41.25,33.575 41.25,33.698 41.25,34.3 44.35,37.4 44.35,38.801 42.45,40.701 v1(42.45,41.875) ; v1(42.55,44) 42.55,43.1 43.05,42.6 43.05,40.998 44.875,39.173 44.875,38.275 v1(45.375,37.775)

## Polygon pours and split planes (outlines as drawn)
3.3V on Top Layer "3.3V_L01_P004" (solid, pour order 4): 60,22.5 59.5,22 59.5,19 57,16.5 43,16.5 42.5,17 28.5,17 26,19.5 26,23 23,23 20.65,25.35 20.65,29.15 23.5,32 25.5,32 26.5,33 27.5,34 29.5,34 29.5,34.5 32.5,37.5 35.5,37.5 41,37.5 44,34.5 44,32.5 43.5,32 41.5,32 41,31.5 41,30.5 41.525,29.975 45.375,29.975 47,31.6 47,36 43,40 32,40 30.5,38.5 28.425,38.5 19,29.075 19,22.125 26.625,14.5 50,14.5 57,14.5 59,12.5 61.5,12.5 62,13 62,22 61.5,22.5
GND on Top Layer "GND_L01_P002" (solid, pour order 2): 45,65.75 73,65.75 73,55.5 70.225,52.725 48.025,52.725 45,55.75
GND on Top Layer "GND_L01_P005" (solid, pour order 5): 0,0 0,19.25 0,121 121,121 121,0
5V on Top Layer "5V_L01_P000" (solid, pour order 0): 45,7 51.5,13.5 55.5,13.5 56.5,12.5 56.5,0.55 45,0.55
GND on Bottom Layer "GND_L02_P006" (solid, pour order 6): 0,0 0,121 121,121 121,0

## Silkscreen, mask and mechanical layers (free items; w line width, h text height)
Top Overlay:
  drawing of 7 lines, arcs and shapes, not listed
  text "PA11" at 36.325,43.45 h1
  text "PA12" at 36.35,41.525 h1
  text "Enc" at 46.1,39.4 h1.2
  text "Inverter" at 111.475,33.275 h1.2
  text "PC15" at 16.625,32.425 h1
  text "Linear Enc" at 113.25,16.575 h1.2
  text "Prog" at 33.2,12.925 h1.2
  text "KSP.01-v02 08.2024" at 82.2,3.2 h2.5
  text "Power" at 48.475,1.025 h1.2
  text "GND" at 66.35,0.25 h1.2
  text "+5V" at 53.4,0.225 h1.2
  text "GND" at 58.7,0.15 h1.2
  text "MDB_N" at 69.875,0.05 h1.2
  text "MDB_P" at 74.7,0.05 h1.2
Bottom Overlay:
  drawing of 7 lines, arcs and shapes, not listed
